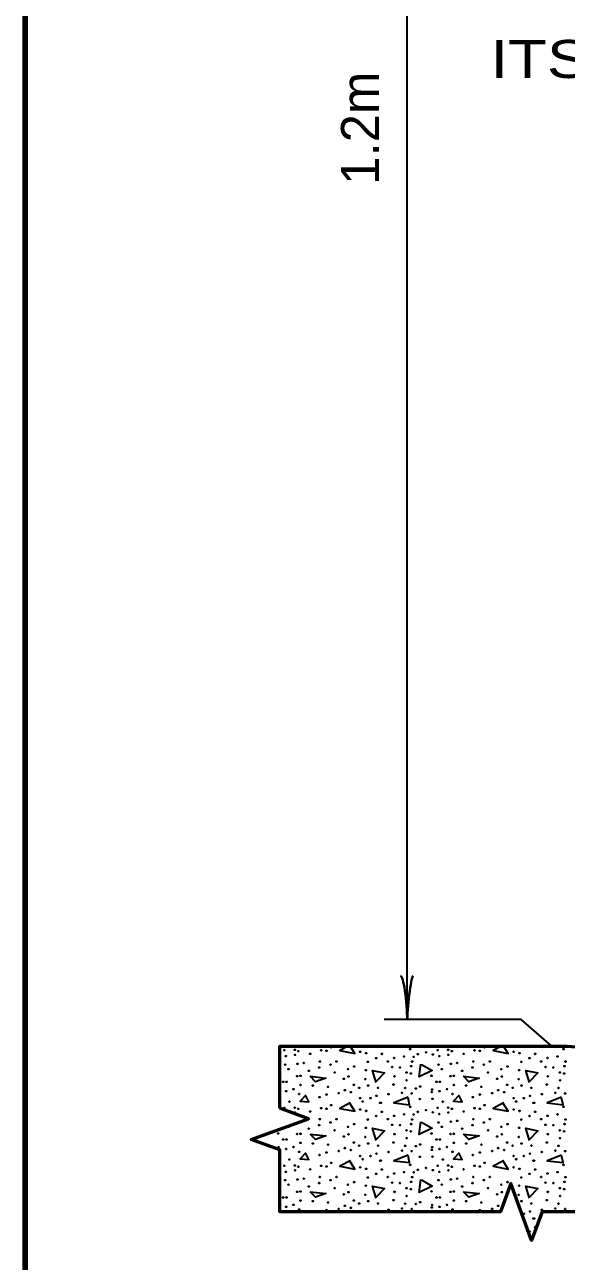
# Model space of a CAD drawing. Extents: x -105 to 751, y -65 to 479.
# Drawn here: x -47.6 to -4.9, y 277.2 to 374.7 of the extents above; entities that cross this region are included whole.
import ezdxf

# ---------------------------------------------------------------- set-up
doc = ezdxf.new("R2010")
doc.units = 0
doc.header["$LTSCALE"] = 1.2
doc.layers.add('1', color=7, linetype='Continuous', lineweight=35)

msp = doc.modelspace()

# ---------------------------------------------------------------- linework, layer by layer
at = {"layer": '1'}
for p, q in [((-17.411, 296.225), (-17.411, 433.734)), ((-28.307, 287.275), (-28.307, 287.275)), ((-25.398, 281.148), (-25.495, 281.046)), ((-25.371, 281.046), (-25.398, 281.1)), ((-13.302, 281.148), (-13.399, 281.046)), ((-13.275, 281.046), (-13.302, 281.1))]:
    msp.add_line(p, q, dxfattribs=at)
at = {"layer": '1', "lineweight": 158}
msp.add_lwpolyline([(744.128, 472.7), (-47.572, 472.6), (-47.472, -53.4)], dxfattribs=at)
at = {"layer": '1', "lineweight": 53}
for points in [[(58.533, 316.446), (102.811, 316.446), (102.811, 359.646), (106.979, 363.962), (141.779, 363.962), (145.947, 359.646), (145.947, 281.046), (120.996, 281.046), (120.176, 278.791), (118.534, 283.301), (117.713, 281.046), (42.713, 281.046), (41.892, 278.791), (40.251, 283.301), (39.43, 281.046), (-6.77, 281.046), (-7.591, 278.791), (-9.232, 283.301), (-10.053, 281.046), (-27.453, 281.046), (-27.453, 285.944), (-29.708, 286.765), (-25.198, 288.406), (-27.453, 289.227)], [(-27.453, 289.227), (-27.453, 294.125), (-4.811, 294.125), (51.451, 290.19), (53.759, 312.148)]]:
    msp.add_lwpolyline(points, dxfattribs=at)
at = {"layer": '1'}
for points in [[(-6.011, 294.125), (-8.411, 296.225), (-19.211, 296.225)], [(-22.063, 294.125), (-22.71, 293.772), (-21.534, 293.556), (-21.9, 294.125)], [(-17.776, 294.125), (-17.214, 294.06), (-17.228, 294.125)], [(-9.967, 294.125), (-10.614, 293.772), (-9.438, 293.556), (-9.804, 294.125)], [(-5.68, 294.125), (-5.118, 294.06), (-5.132, 294.125)], [(-16.278, 292.692), (-15.438, 292.212), (-16.47, 291.708), (-16.326, 292.716)], [(-19.854, 291.252), (-20.142, 292.212), (-19.206, 292.02), (-19.878, 291.3)], [(-7.758, 291.252), (-8.046, 292.212), (-7.11, 292.02), (-7.782, 291.3)], [(-25.398, 290.268), (-25.854, 289.788), (-25.158, 289.74), (-25.398, 290.22)], [(-17.334, 290.1), (-18.462, 289.644), (-17.214, 289.5), (-17.334, 290.052)], [(-13.302, 290.268), (-13.758, 289.788), (-13.062, 289.74), (-13.302, 290.22)], [(-5.238, 290.1), (-6.366, 289.644), (-5.118, 289.5), (-5.238, 290.052)], [(-21.918, 289.644), (-22.71, 289.212), (-21.534, 288.996), (-21.966, 289.668)], [(-9.822, 289.644), (-10.614, 289.212), (-9.438, 288.996), (-9.87, 289.668)], [(-16.278, 288.132), (-15.438, 287.652), (-16.47, 287.148), (-16.326, 288.156)], [(-28.307, 287.275), (-28.566, 287.148), (-28.561, 287.182)], [(-19.854, 286.692), (-20.142, 287.652), (-19.206, 287.46), (-19.878, 286.74)], [(-7.758, 286.692), (-8.046, 287.652), (-7.11, 287.46), (-7.782, 286.74)], [(-25.398, 285.708), (-25.854, 285.228), (-25.158, 285.18), (-25.398, 285.66)], [(-21.918, 285.084), (-22.71, 284.652), (-21.534, 284.436), (-21.966, 285.108)], [(-17.334, 285.54), (-18.462, 285.084), (-17.214, 284.94), (-17.334, 285.492)], [(-13.302, 285.708), (-13.758, 285.228), (-13.062, 285.18), (-13.302, 285.66)], [(-9.822, 285.084), (-10.614, 284.652), (-9.438, 284.436), (-9.87, 285.108)], [(-5.238, 285.54), (-6.366, 285.084), (-5.118, 284.94), (-5.238, 285.492)], [(-19.854, 282.132), (-20.142, 283.092), (-19.206, 282.9), (-19.878, 282.18)], [(-16.278, 283.572), (-15.438, 283.092), (-16.47, 282.588), (-16.326, 283.596)], [(-7.758, 282.132), (-8.046, 283.092), (-7.11, 282.9), (-7.782, 282.18)]]:
    msp.add_lwpolyline(points, dxfattribs=at)
for points in [[(-25.062, 291.756), (-23.814, 291.612), (-24.63, 291.324)], [(-12.966, 291.756), (-11.718, 291.612), (-12.534, 291.324)], [(-25.062, 287.196), (-23.814, 287.052), (-24.63, 286.764)], [(-12.966, 287.196), (-11.718, 287.052), (-12.534, 286.764)], [(-25.062, 282.636), (-23.814, 282.492), (-24.63, 282.204)], [(-12.966, 282.636), (-11.718, 282.492), (-12.534, 282.204)]]:
    msp.add_lwpolyline(points, close=True, dxfattribs=at)
for centre in [(-27.098, 293.815), (-26.271, 293.831), (-25.991, 293.735), (-24.194, 293.799), (-23.78, 293.751), (-23.399, 294.038), (-21.109, 293.688), (-20.647, 293.576), (-17.18, 293.894), (-15.924, 293.64), (-15.002, 293.815), (-14.175, 293.831), (-13.895, 293.735), (-12.098, 293.799), (-11.684, 293.751), (-11.303, 294.038), (-9.013, 293.688), (-8.551, 293.576), (-5.084, 293.894), (-27.034, 292.669), (-26.97, 293.338), (-26.255, 293.449), (-26.064, 292.733), (-25.562, 292.797), (-25.053, 293.528), (-24.289, 292.924), (-23.462, 292.669), (-22.985, 292.924), (-20.504, 292.892), (-19.852, 293.179), (-19.407, 293.513), (-18.93, 292.924), (-18.437, 293.194), (-17.658, 293.306), (-17.021, 292.908), (-16.894, 293.29), (-16.56, 293.497), (-15.383, 293.465), (-14.938, 292.669), (-14.874, 293.338), (-14.159, 293.449), (-13.968, 292.733), (-13.466, 292.797), (-12.957, 293.528), (-12.193, 292.924), (-11.366, 292.669), (-10.889, 292.924), (-8.408, 292.892), (-7.756, 293.179), (-7.311, 293.513), (-6.834, 292.924), (-6.341, 293.194), (-5.562, 293.306), (-4.925, 292.908), (-26.764, 292.319), (-26.088, 291.76), (-25.816, 291.779), (-25.164, 292.176), (-24.353, 292.447), (-23.128, 292.049), (-22.079, 292.319), (-22.031, 291.731), (-21.586, 292.526), (-20.663, 292.24), (-18.596, 292.479), (-18.405, 291.747), (-17.976, 292.447), (-17.467, 292.049), (-17.117, 291.969), (-17.101, 292.542), (-15.495, 291.794), (-14.668, 292.319), (-13.992, 291.76), (-13.72, 291.779), (-13.068, 292.176), (-12.257, 292.447), (-11.032, 292.049), (-9.983, 292.319), (-9.935, 291.731), (-9.49, 292.526), (-8.567, 292.24), (-6.5, 292.479), (-6.309, 291.747), (-5.88, 292.447), (-5.371, 292.049), (-5.021, 291.969), (-5.005, 292.542), (-27.193, 291.317), (-26.923, 291.317), (-26.366, 290.729), (-25.816, 291.063), (-24.846, 291.015), (-23.653, 290.919), (-22.413, 291.556), (-22.333, 290.649), (-21.618, 291.079), (-21.188, 290.84), (-20.711, 291.524), (-20.488, 291.015), (-19.709, 290.84), (-18.485, 291.094), (-17.562, 290.824), (-17.451, 291.429), (-16.719, 290.792), (-16.385, 290.935), (-15.447, 290.713), (-15.097, 291.317), (-14.827, 291.317), (-14.27, 290.729), (-13.72, 291.063), (-12.75, 291.015), (-11.557, 290.919), (-10.317, 291.556), (-10.237, 290.649), (-9.522, 291.079), (-9.092, 290.84), (-8.615, 291.524), (-8.392, 291.015), (-7.613, 290.84), (-6.389, 291.094), (-5.466, 290.824), (-5.355, 291.429), (-26.955, 290.575), (-26.7, 289.748), (-25.927, 290.353), (-24.321, 290.098), (-23.78, 290.305), (-22.81, 290.416), (-21.856, 290.496), (-21.109, 290.019), (-20.918, 289.764), (-20.298, 290.019), (-19.82, 290.209), (-18.882, 290.337), (-17.817, 290.448), (-17.053, 290.4), (-16.417, 289.955), (-15.463, 290.512), (-15.415, 289.971), (-14.859, 290.575), (-14.604, 289.748), (-13.831, 290.353), (-12.225, 290.098), (-11.684, 290.305), (-10.714, 290.416), (-9.76, 290.496), (-9.013, 290.019), (-8.822, 289.764), (-8.202, 290.019), (-7.724, 290.209), (-6.786, 290.337), (-5.721, 290.448), (-4.957, 290.4), (-27.098, 289.255), (-26.271, 289.271), (-26.255, 288.889), (-25.991, 289.175), (-25.053, 288.968), (-24.194, 289.239), (-23.78, 289.191), (-23.399, 289.478), (-21.109, 289.128), (-20.647, 289.016), (-19.55, 289.653), (-19.486, 289.653), (-19.407, 288.953), (-17.658, 288.746), (-17.18, 289.334), (-16.894, 288.73), (-16.56, 288.937), (-15.924, 289.08), (-15.383, 288.905), (-15.002, 289.255), (-14.874, 288.778), (-14.175, 289.271), (-14.159, 288.889), (-13.895, 289.175), (-12.957, 288.968), (-12.098, 289.239), (-11.684, 289.191), (-11.303, 289.478), (-9.013, 289.128), (-8.551, 289.016), (-7.454, 289.653), (-7.39, 289.653), (-7.311, 288.953), (-5.562, 288.746), (-5.084, 289.334), (-26.764, 287.759), (-25.562, 288.237), (-24.353, 287.887), (-24.289, 288.364), (-23.462, 288.109), (-22.985, 288.364), (-22.079, 287.759), (-21.586, 287.966), (-20.504, 288.332), (-19.852, 288.619), (-18.93, 288.364), (-18.596, 287.919), (-18.437, 288.634), (-17.976, 287.887), (-17.101, 287.982), (-17.021, 288.348), (-14.938, 288.109), (-14.668, 287.759), (-13.968, 288.173), (-13.466, 288.237), (-12.257, 287.887), (-12.193, 288.364), (-11.366, 288.109), (-10.889, 288.364), (-9.983, 287.759), (-9.49, 287.966), (-8.408, 288.332), (-7.756, 288.619), (-6.834, 288.364), (-6.5, 287.919), (-6.341, 288.634), (-5.88, 287.887), (-5.005, 287.982), (-4.925, 288.348), (-27.591, 287.234), (-27.193, 286.757), (-26.923, 286.757), (-26.088, 287.2), (-25.816, 287.219), (-25.164, 287.616), (-23.128, 287.489), (-22.413, 286.996), (-22.031, 287.171), (-20.711, 286.964), (-20.663, 287.68), (-18.405, 287.187), (-17.467, 287.489), (-17.451, 286.869), (-17.117, 287.409), (-15.495, 287.234), (-15.097, 286.757), (-14.827, 286.757), (-13.992, 287.2), (-13.72, 287.219), (-13.068, 287.616), (-11.032, 287.489), (-10.317, 286.996), (-9.935, 287.171), (-8.615, 286.964), (-8.567, 287.68), (-6.309, 287.187), (-5.371, 287.489), (-5.355, 286.869), (-5.021, 287.409), (-28.481, 286.375), (-27.543, 286.153), (-26.955, 286.015), (-26.366, 286.169), (-25.927, 285.793), (-25.816, 286.503), (-24.846, 286.455), (-23.653, 286.359), (-22.81, 285.856), (-22.333, 286.089), (-21.856, 285.936), (-21.618, 286.519), (-21.188, 286.28), (-20.488, 286.455), (-19.709, 286.28), (-18.882, 285.777), (-18.485, 286.534), (-17.817, 285.888), (-17.562, 286.264), (-17.053, 285.84), (-16.719, 286.232), (-16.385, 286.375), (-15.463, 285.952), (-15.447, 286.153), (-14.859, 286.015), (-14.27, 286.169), (-13.831, 285.793), (-13.72, 286.503), (-12.75, 286.455), (-11.557, 286.359), (-10.714, 285.856), (-10.237, 286.089), (-9.76, 285.936), (-9.522, 286.519), (-9.092, 286.28), (-8.392, 286.455), (-7.613, 286.28), (-6.786, 285.777), (-6.389, 286.534), (-5.721, 285.888), (-5.466, 286.264), (-4.957, 285.84), (-26.7, 285.188), (-24.321, 285.538), (-23.78, 285.745), (-23.399, 284.918), (-21.109, 285.459), (-20.918, 285.204), (-20.298, 285.459), (-19.82, 285.649), (-19.55, 285.093), (-19.486, 285.093), (-16.417, 285.395), (-15.415, 285.411), (-14.604, 285.188), (-12.225, 285.538), (-11.684, 285.745), (-11.303, 284.918), (-9.013, 285.459), (-8.822, 285.204), (-8.202, 285.459), (-7.724, 285.649), (-7.454, 285.093), (-7.39, 285.093), (-27.098, 284.695), (-26.97, 284.218), (-26.271, 284.711), (-26.255, 284.329), (-25.991, 284.615), (-25.053, 284.408), (-24.194, 284.679), (-23.78, 284.631), (-21.109, 284.568), (-20.647, 284.456), (-19.852, 284.059), (-19.407, 284.393), (-18.437, 284.074), (-17.658, 284.186), (-17.18, 284.774), (-16.894, 284.17), (-16.56, 284.377), (-15.924, 284.52), (-15.383, 284.345), (-15.002, 284.695), (-14.874, 284.218), (-14.175, 284.711), (-14.159, 284.329), (-13.895, 284.615), (-12.957, 284.408), (-12.098, 284.679), (-11.684, 284.631), (-9.013, 284.568), (-8.551, 284.456), (-7.756, 284.059), (-7.311, 284.393), (-6.341, 284.074), (-5.562, 284.186), (-5.084, 284.774), (-27.034, 283.549), (-26.764, 283.199), (-26.064, 283.613), (-25.562, 283.677), (-25.164, 283.056), (-24.353, 283.327), (-24.289, 283.804), (-23.462, 283.549), (-23.128, 282.929), (-22.985, 283.804), (-22.079, 283.199), (-21.586, 283.406), (-20.663, 283.12), (-20.504, 283.772), (-18.93, 283.804), (-18.596, 283.359), (-17.976, 283.327), (-17.467, 282.929), (-17.117, 282.849), (-17.101, 283.422), (-17.021, 283.788), (-14.938, 283.549), (-14.668, 283.199), (-13.968, 283.613), (-13.466, 283.677), (-13.068, 283.056), (-12.257, 283.327), (-12.193, 283.804), (-11.366, 283.549), (-11.032, 282.929), (-10.889, 283.804), (-9.983, 283.199), (-9.49, 283.406), (-8.567, 283.12), (-8.408, 283.772), (-6.834, 283.804), (-6.5, 283.359), (-5.88, 283.327), (-5.371, 282.929), (-5.021, 282.849), (-5.005, 283.422), (-4.925, 283.788), (-27.193, 282.197), (-26.923, 282.197), (-26.088, 282.64), (-25.816, 282.659), (-25.816, 281.943), (-24.846, 281.895), (-22.413, 282.436), (-22.031, 282.611), (-21.618, 281.959), (-20.711, 282.404), (-20.488, 281.895), (-18.485, 281.974), (-18.405, 282.627), (-17.451, 282.309), (-15.495, 282.674), (-15.097, 282.197), (-14.827, 282.197), (-13.992, 282.64), (-13.72, 282.659), (-13.72, 281.943), (-12.75, 281.895), (-10.317, 282.436), (-9.935, 282.611), (-8.615, 282.404), (-8.392, 281.895), (-6.389, 281.974), (-6.309, 282.627), (-5.355, 282.309), (-26.955, 281.455), (-26.366, 281.609), (-25.927, 281.233), (-23.78, 281.185), (-23.653, 281.799), (-22.81, 281.296), (-22.333, 281.529), (-21.856, 281.376), (-21.188, 281.72), (-19.82, 281.089), (-19.709, 281.72), (-18.882, 281.217), (-17.817, 281.328), (-17.562, 281.704), (-17.053, 281.28), (-16.719, 281.672), (-16.385, 281.815), (-15.463, 281.392), (-15.447, 281.593), (-14.859, 281.455), (-14.27, 281.609), (-13.831, 281.233), (-11.684, 281.185), (-11.557, 281.799), (-10.714, 281.296), (-10.237, 281.529), (-8.202, 280.899), (-7.724, 281.089), (-7.613, 281.72), (-6.786, 281.217), (-5.721, 281.328), (-5.466, 281.704), (-4.957, 281.28), (-7.454, 280.533), (-7.39, 280.533), (-7.756, 279.499), (-7.311, 279.833)]:
    msp.add_circle(centre, 0.0318, dxfattribs=at)
for centre, start, end in [((-27.479, 293.465), 325.24736, 34.75264), ((-27.559, 285.952), 44.9547, 95.04645), ((-27.479, 284.345), 325.24736, 34.75264)]:
    msp.add_arc(centre, 0.0318, start, end, dxfattribs=at)
at = {"layer": '1', "lineweight": 40}
for centre, major_axis, ratio, start_param, end_param in [((-17.743, 297.534), (0.187, -2.143), 0.122415, 0.896353, 3.141593), ((-17.743, 297.534), (0.187, -2.143), 0.122415, 0.896353, 3.141593), ((-17.157, 297.569), (-0.211, -2.108), 0.07063, 3.140715, 5.41811), ((-17.157, 297.569), (-0.211, -2.108), 0.07063, 3.140715, 5.41811)]:
    msp.add_ellipse(centre, major_axis=major_axis, ratio=ratio, start_param=start_param, end_param=end_param, dxfattribs=at)

# ---------------------------------------------------------------- texts
at = {"layer": '1', "width": 1.25}
msp.add_text('ITS TYPE "A" BRACKET. ', height=3, dxfattribs=at).set_placement((-10.846, 370.5))
at = {"layer": '1'}
msp.add_text('1.2m', height=3, rotation=90, dxfattribs=at).set_placement((-19.627, 362.078))

doc.saveas('drawing.dxf')
